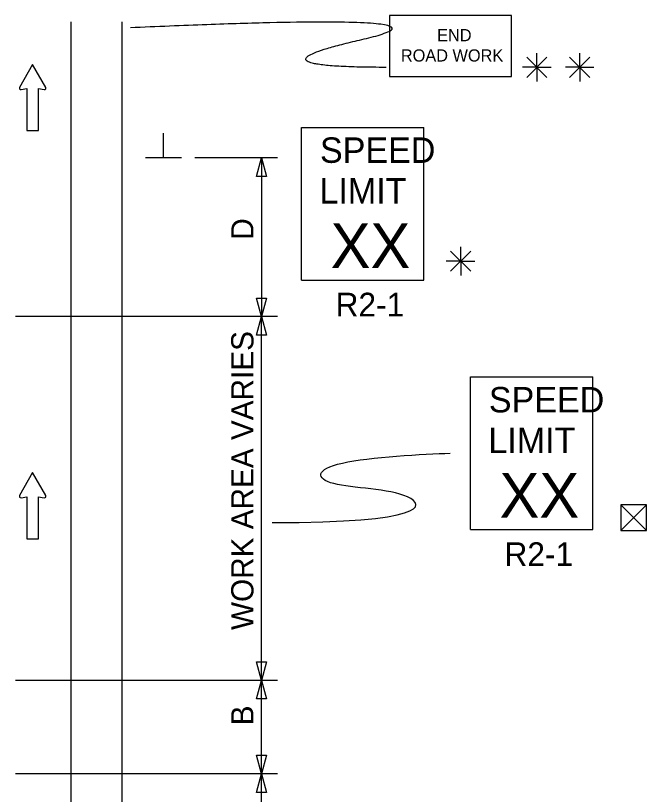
# Model space of a CAD drawing. Extents: x 16724 to 19508, y 5703 to 6974.
# Drawn here: x 17971.6 to 18170, y 6682 to 6927.3 of the extents above; entities that cross this region are included whole.
import ezdxf

# ---------------------------------------------------------------- set-up
doc = ezdxf.new("R2010")
doc.units = 0
for name, color, linetype in [('MT_SCRATCH_LEVEL_E', 7, 'Continuous'), ('PAVT_EDGE_EX', 7, 'Continuous'), ('TRAFFIC_SIGNS_PR', 7, 'Continuous'), ('TYPICAL_TEXT_DIMEN_PR', 7, 'Continuous')]:
    doc.layers.add(name, color=color, linetype=linetype)

msp = doc.modelspace()

# ---------------------------------------------------------------- linework, layer by layer
at = {"layer": 'MT_SCRATCH_LEVEL_E'}
for p, q in [((17976.91, 6911.94), (17972.8, 6904.69)), ((17981.06, 6904.69), (17976.91, 6911.94)), ((17973.28, 6904.01), (17975.06, 6904.32)), ((17975.06, 6904.32), (17975.06, 6891.07)), ((17978.8, 6891.07), (17978.8, 6904.32)), ((17978.8, 6904.32), (17980.58, 6904.01)), ((17975.06, 6891.07), (17978.8, 6891.07)), ((17976.91, 6783.4), (17972.8, 6776.16)), ((17981.06, 6776.16), (17976.91, 6783.4)), ((17973.28, 6775.48), (17975.06, 6775.79)), ((17975.06, 6775.79), (17975.06, 6762.53)), ((17978.8, 6762.53), (17978.8, 6775.79)), ((17978.8, 6775.79), (17980.58, 6775.48)), ((17975.06, 6762.53), (17978.8, 6762.53))]:
    msp.add_line(p, q, dxfattribs=at)
for centre, start, end in [((17973.21, 6904.47), 150.4248, 279.9638), ((17980.65, 6904.47), 260.0362, 29.7731), ((17973.21, 6775.94), 150.4248, 279.9638), ((17980.65, 6775.94), 260.0362, 29.7731)]:
    msp.add_arc(centre, 0.463, start, end, dxfattribs=at)
at = {"layer": 'PAVT_EDGE_EX'}
for p, q in [((17988.96, 6925.33), (17988.96, 6103.04)), ((18004.96, 6925.33), (18004.96, 6103.04))]:
    msp.add_line(p, q, dxfattribs=at)
at = {"layer": 'TRAFFIC_SIGNS_PR'}
for p, q in [((18061.55, 6892.08), (18100, 6892.08)), ((18061.55, 6844.02), (18061.55, 6892.08)), ((18100, 6844.02), (18100, 6892.08)), ((18061.55, 6844.02), (18100, 6844.02)), ((18114.69, 6813.49), (18153.14, 6813.49)), ((18114.69, 6765.44), (18114.69, 6813.49)), ((18153.14, 6765.44), (18153.14, 6813.49)), ((18114.69, 6765.44), (18153.14, 6765.44))]:
    msp.add_line(p, q, dxfattribs=at)
msp.add_lwpolyline([(18089.17, 6908.08), (18127.62, 6908.08), (18127.62, 6927.31), (18089.17, 6927.31)], close=True, dxfattribs=at)
msp.add_open_spline([(18088.12, 6911), (18041.94, 6910.99), (18118.46, 6928.4), (18007.67, 6923.46)], degree=2, dxfattribs=at)
at = {"layer": 'TYPICAL_TEXT_DIMEN_PR'}
for p, q in [((18135.54, 6911.02), (18135.54, 6915.48)), ((18149.05, 6911.02), (18149.05, 6915.48)), ((18132.36, 6914.21), (18138.73, 6907.83)), ((18138.73, 6914.21), (18132.36, 6907.83)), ((18145.86, 6914.21), (18152.24, 6907.83)), ((18152.24, 6914.21), (18145.86, 6907.83)), ((18135.54, 6911.02), (18131.01, 6911.02)), ((18135.54, 6911.02), (18138.73, 6911.02)), ((18135.54, 6911.02), (18140.02, 6911.02)), ((18135.54, 6911.02), (18135.54, 6906.52)), ((18149.05, 6911.02), (18144.52, 6911.02)), ((18149.05, 6911.02), (18152.24, 6911.02)), ((18149.05, 6911.02), (18153.53, 6911.02)), ((18149.05, 6911.02), (18149.05, 6906.52)), ((18018.08, 6882.5), (18018.08, 6890.28)), ((18023.71, 6882.5), (18012.46, 6882.5)), ((18053.96, 6882.5), (18027.96, 6882.5)), ((18047.39, 6876.64), (18048.96, 6882.5)), ((18048.96, 6882.5), (18048.96, 6832.5)), ((18048.96, 6882.5), (18050.53, 6876.64)), ((18048.96, 6876.64), (18047.39, 6876.64)), ((18050.53, 6876.64), (18048.96, 6876.64)), ((18108.41, 6853.16), (18114.78, 6846.78)), ((18114.78, 6853.16), (18108.41, 6846.78)), ((18111.6, 6849.97), (18111.6, 6854.43)), ((18111.6, 6849.97), (18107.06, 6849.97)), ((18111.6, 6849.97), (18114.78, 6849.97)), ((18111.6, 6849.97), (18116.07, 6849.97)), ((18111.6, 6849.97), (18111.6, 6845.47)), ((18048.96, 6832.5), (18047.39, 6838.36)), ((18047.39, 6838.36), (18048.96, 6838.36)), ((18048.96, 6838.36), (18050.53, 6838.36)), ((18050.53, 6838.36), (18048.96, 6832.5)), ((18053.96, 6832.5), (17971.56, 6832.5)), ((18047.39, 6826.64), (18048.96, 6832.5)), ((18048.96, 6717.96), (18048.96, 6832.5)), ((18048.96, 6832.5), (18050.53, 6826.64)), ((18048.96, 6826.64), (18047.39, 6826.64)), ((18050.53, 6826.64), (18048.96, 6826.64)), ((18162.02, 6773.18), (18170.02, 6765.18)), ((18162.02, 6765.18), (18170.02, 6773.18)), ((18048.96, 6717.96), (18047.39, 6723.83)), ((18047.39, 6723.83), (18048.96, 6723.83)), ((18048.96, 6723.83), (18050.53, 6723.83)), ((18050.53, 6723.83), (18048.96, 6717.96)), ((18053.96, 6717.96), (17971.56, 6717.96)), ((18047.39, 6712.1), (18048.96, 6717.96)), ((18048.96, 6688.54), (18048.96, 6717.96)), ((18048.96, 6717.96), (18050.53, 6712.1)), ((18048.96, 6712.1), (18047.39, 6712.1)), ((18050.53, 6712.1), (18048.96, 6712.1)), ((18048.96, 6688.54), (18047.39, 6694.4)), ((18047.39, 6694.4), (18048.96, 6694.4)), ((18048.96, 6694.4), (18050.53, 6694.4)), ((18050.53, 6694.4), (18048.96, 6688.54)), ((18053.96, 6688.54), (17971.56, 6688.54)), ((18047.39, 6682.67), (18048.96, 6688.54)), ((18048.96, 6657.97), (18048.96, 6688.54)), ((18048.96, 6688.54), (18050.53, 6682.67)), ((18048.96, 6682.67), (18047.39, 6682.67)), ((18050.53, 6682.67), (18048.96, 6682.67))]:
    msp.add_line(p, q, dxfattribs=at)
msp.add_lwpolyline([(18162.02, 6773.18), (18162.02, 6765.18), (18170.02, 6765.18), (18170.02, 6773.18)], close=True, dxfattribs=at)
msp.add_open_spline([(18052.27, 6767.65), (18100.73, 6767.65), (18100.73, 6778.4), (18065.82, 6778.4), (18065.82, 6787.45), (18100.02, 6789.22), (18108.31, 6789.51)], degree=3, dxfattribs=at)

# ---------------------------------------------------------------- texts
at = {"layer": 'TRAFFIC_SIGNS_PR'}
for s, height, p in [('END', 3.836, (18104.19, 6919.22)), ('ROAD WORK', 3.836, (18092.78, 6912.83)), ('SPEED', 8.01, (18067.33, 6880.93)), ('LIMIT', 8.01, (18067.16, 6868.12)), ('XX', 14.048, (18070.68, 6847.79)), ('R2-1', 7.449, (18072.24, 6832.57)), ('SPEED', 8.01, (18120.46, 6802.34)), ('LIMIT', 8.01, (18120.3, 6789.53)), ('XX', 14.048, (18123.81, 6769.2)), ('R2-1', 7.449, (18125.38, 6753.98))]:
    msp.add_text(s, height=height, dxfattribs=at).set_placement(p)
at = {"layer": 'TYPICAL_TEXT_DIMEN_PR'}
for s, p in [('D', (18046.4, 6856.72)), ('WORK AREA VARIES', (18046.4, 6733.81)), ('B', (18046.4, 6703.8))]:
    msp.add_text(s, height=7, rotation=90, dxfattribs=at).set_placement(p)

doc.saveas('drawing.dxf')
